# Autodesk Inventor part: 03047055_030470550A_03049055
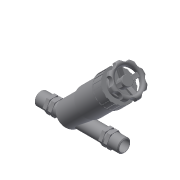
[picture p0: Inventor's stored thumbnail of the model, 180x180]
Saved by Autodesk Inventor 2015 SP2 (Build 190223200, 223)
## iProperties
Created: 2017-05
Part Number: 03047055_030470550A_03049055
Material: Generic
Description: PLASSON ANGLE SEAT VALVE 1/2"
Document SubType Name: Modeling
Designer: KIM
Density: 1 g/cm^3
Appearance: Default
Author: KIM
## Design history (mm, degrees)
derived "03049.ipt"
feature "Solid1::03049.ipt"
tag "TaggingFeature1"
body "Solid1"
other parameters: "d0" = 135, "d1" = 20.955, "d2" = 22, "d3" = 16.764, "d4" = 16, "d5" = 16, "d6" = 13.5, "d8" = 1.35, "d12" = 0, "d14" = -6.75, "d15" = 2.7, "d16" = 0, "d17" = 33.561, "d18" = 4.068, "d19" = 111.87, "d20" = 38.1375, "d21" = 135 deg, "d22" = 43.2225, "d23" = 20.34, "d24" = 48.3075, "d25" = 12.204, "d26" = 90 deg, "d27" = 35.595, "d28" = 70 deg, "d29" = 15.255, "d30" = 12.204, "d31" = 15.255, "d32" = 50.85, "d33" = 35.595, "d34" = 135 deg, "d35" = 2, "d36" = 101.7, "d39" = 47.25, "d40" = 1.13, "d41" = 1, "d42" = 2, "d43" = 3.39, "d44" = 3.39, "d46" = 0, "d48" = 360 deg, "d50" = 0.565, "d51" = 0.565, "d53" = 360 deg, "d69" = 43.2225, "d70" = 3.39, "d71" = 3.39, "d72" = 6.78, "d74" = 0, "d75" = 0.565, "d77" = 360 deg, "d80" = 46.85828, "d81" = 4.52, "d82" = 2.26, "d83" = 18.306, "d84" = 0, "d86" = 360 deg, "d88" = 1.13, "d91" = 113, "H_" = 135, "R_" = 20.955, "E_" = 22, "l_2" = 16, "A_" = 113, "d13" = 13.5, "d67" = 50.85, "d68" = 35.595, "d79" = 48.3075
